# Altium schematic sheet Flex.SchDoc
size 431 x 279 mm; Organization: ORGANIZATION; Address1: ADDRESS 1; Address2: ADDRESS 2; Address3: ADDRESS 3; Address4: ADDRESS 4; Revision: -; ENG_APP_DATE: --/--/--; DSN_APP_DATE: --/--/--; CHK_APP_DATE: --/--/--
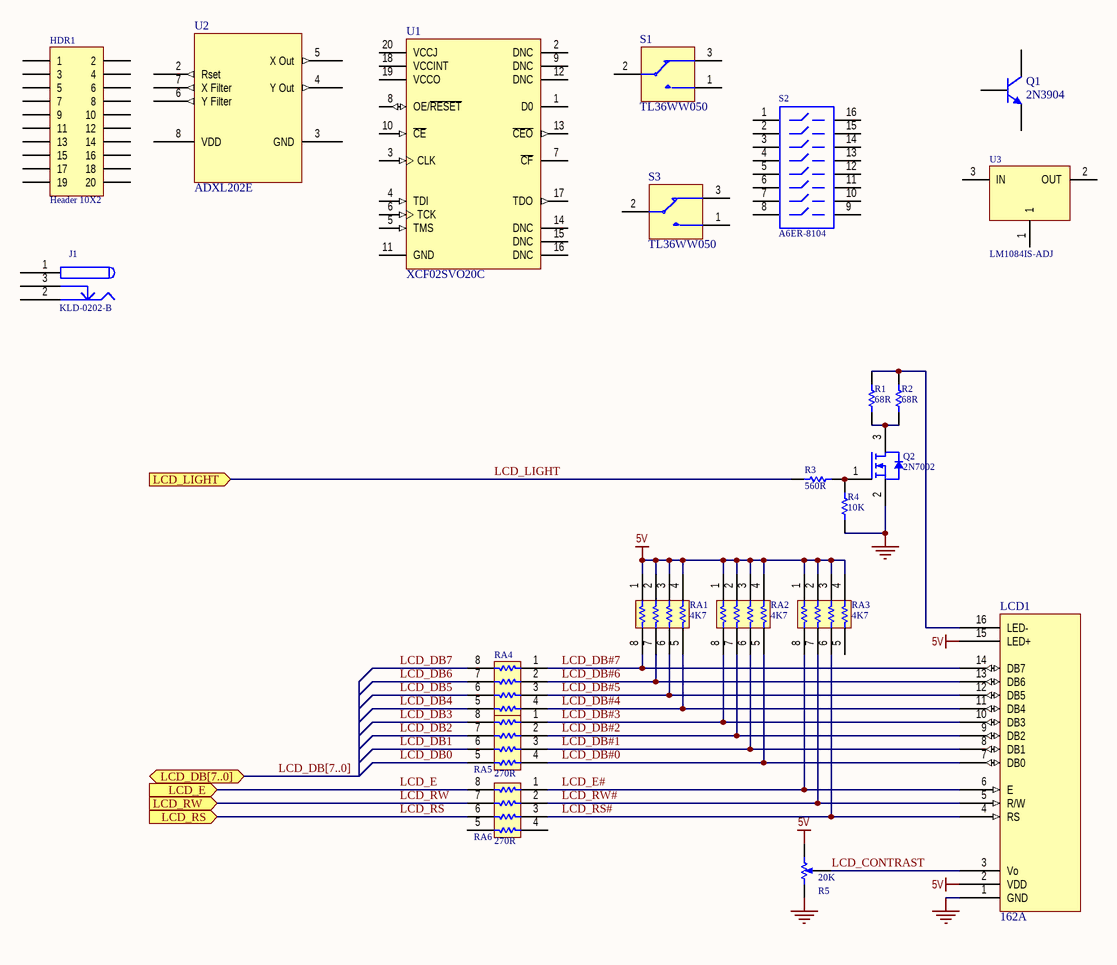
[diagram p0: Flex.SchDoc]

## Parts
HDR1  Header 10X2  [HDR2X10]
J1  KLD-0202-B  [KLD-0202]
LCD1  162A  [162A]
Q1  2N3904  [TO-92A]
Q2  2N7002  [SO-G3]
R1  68R  [CC2012-0805]
R2  68R  [CC2012-0805]
R3  560R  [CC2012-0805]
R4  10K  [CR2012-0805]
R5  20K  [POT4MM-2]
RA1  4K7  [MNR34T]
RA2  4K7  [MNR34T]
RA3  4K7  [MNR34T]
RA4  270R  [MNR34]
RA5  270R  [MNR34]
RA6  270R  [MNR34]
S1  TL36WW050  [PCB_SWITCH]
S2  A6ER-8104  [DIP-16-KEY]
S3  TL36WW050  [PCB_SWITCH]
U1  XCF02SVO20C  [VO20]
U2  ADXL202E  [E-8]
U3  LM1084IS-ADJ  [TO-263]

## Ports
LCD_DB[7..0] (bidir), LCD_E (in), LCD_LIGHT (in), LCD_RS (in), LCD_RW (in)

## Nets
5V: LCD1.2(VDD) LCD1.15(LED+) R5.CW(+) RA1.1 RA1.2 RA1.3 RA1.4 RA2.1 RA2.2 RA2.3 RA2.4 RA3.1 RA3.2 RA3.3 RA3.4
GND: LCD1.1(GND) Q2.2 R4.1 R5.CCW(-)
LCD_CONTRAST: LCD1.3(Vo) R5.W
LCD_DB0: RA5.5
LCD_DB1: RA5.6
LCD_DB2: RA5.7
LCD_DB3: RA5.8
LCD_DB4: RA4.5
LCD_DB5: RA4.6
LCD_DB6: RA4.7
LCD_DB7: RA4.8
LCD_DB#0: LCD1.7(DB0) RA2.5 RA5.4
LCD_DB#1: LCD1.8(DB1) RA2.6 RA5.3
LCD_DB#2: LCD1.9(DB2) RA2.7 RA5.2
LCD_DB#3: LCD1.10(DB3) RA2.8 RA5.1
LCD_DB#4: LCD1.11(DB4) RA1.5 RA4.4
LCD_DB#5: LCD1.12(DB5) RA1.6 RA4.3
LCD_DB#6: LCD1.13(DB6) RA1.7 RA4.2
LCD_DB#7: LCD1.14(DB7) RA1.8 RA4.1
LCD_E: RA6.8 ; port LCD_E
LCD_E#: LCD1.6(E) RA3.8 RA6.1
LCD_LIGHT: R3.1 ; port LCD_LIGHT
LCD_RS: RA6.6 ; port LCD_RS
LCD_RS#: LCD1.4(RS) RA3.6 RA6.3
LCD_RW: RA6.7 ; port LCD_RW
LCD_RW#: LCD1.5(R/W) RA3.7 RA6.2
NetLCD1_16: LCD1.16(LED-) R1.1 R2.1
NetQ2_1: Q2.1 R3.2 R4.2
NetQ2_3: Q2.3 R1.2 R2.2

Not connected (* = marked no-connect by the designer): HDR1 1 2 3 4 5 6 7 8 9 10 11 12 13 14 15 16 17 18 19 20; J1 1 2 3; Q1 1(E) 2(B) 3(C); RA3 5; RA6 4 5; S1 1 2 3; S2 1 2 3 4 5 6 7 8 9 10 11 12 13 14 15 16; S3 1 2 3; U1 1(D0) 2(DNC) 3(CLK) 4(TDI) 5(TMS) 6(TCK) 7(~{CF}) 8(OE/~{RESET}) 9(DNC) 10(~{CE}) 11(GND) 12(DNC) 13(~{CEO}) 14(DNC) 15(DNC) 16(DNC) 17(TDO) 18(VCCINT) 19(VCCO) 20(VCCJ); U2 1(Self_Test) 2(Rset) 3(GND) 4(Y_Out) 5(X_Out) 6(Y_Filter) 7(X_Filter) 8(VDD); U3 1 2(OUT) 3(IN)

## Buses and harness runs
bus LCD_DB[7..0] = port LCD_DB[7..0]

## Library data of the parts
HDR1 = Header 10X2: Header, 10-Pin, Dual row
J1 = KLD-0202-B: Low Voltage Power Supply Connector; Manufacturer: Kycon; AEMS Code: 3510211
LCD1 = 162A: 16 char * 2 line LCD character display with b/light
Q1 = 2N3904: NPN General Purpose Amplifier
Q2 = 2N7002: N Channel Mosfet
R1 R2 = RES_2: Resistor; AEMS Code: 1200821
R3 = RES: Resistor; AEMS Code: 1200723
R4 = RES: Resistor; AEMS Code: 1200006JT
R5 = RPot SM: Square Trimming Potentiometer; AEMS Code: 1400226
RA1-RA3 = MNR34: 3216x4 Resistor Array; AEMS Code: 1300330
RA4-RA6 = MNR34: 3216x4 Resistor Array; AEMS Code: 1310010
S1 S3 = PCB_MOUNT_SWITCH: SPDT Subminiature Toggle Switch
S2 = A6ER-8104: DIP Switch Side actuator long liver Piano Key
U1 = XCF02SVO20C: XCF00S Series, Platform Flash In-System Programmable Configuration 3.3V PROM, 20-Pin TSOP, 2-Megabit, Commercial Grade; PackageDocument: ver1.0, May-2003; AEMS Code: CHANGED VALUE
U2 = ADXL202E: Accelerometer with Digital Output
U3 = LM1084IS-ADJ: 5A Low Dropout Possitive Regulators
